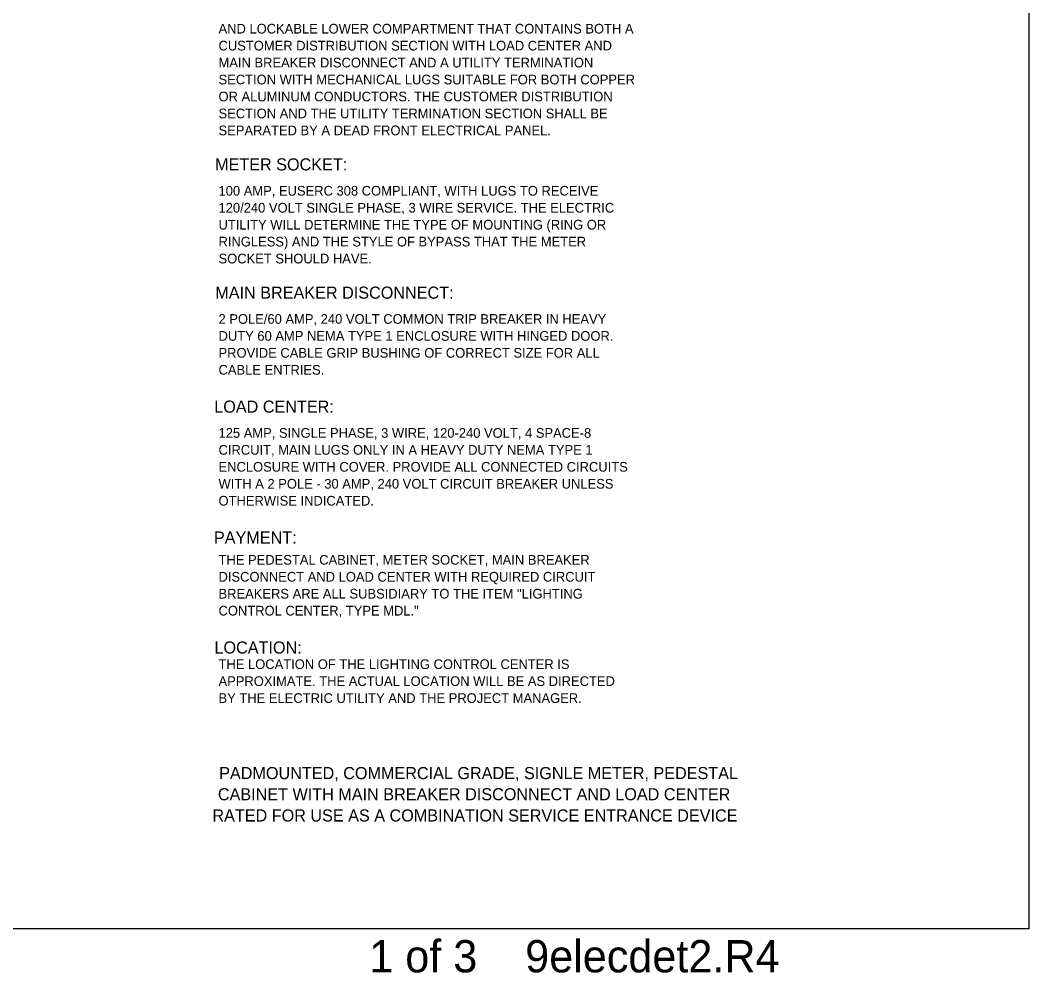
# Model space of a CAD drawing. Extents: x 99992 to 113392, y 99794 to 102182.
# Drawn here: x 101942 to 103192, y 99831 to 101011 of the extents above; entities that cross this region are included whole.
import ezdxf

# ---------------------------------------------------------------- set-up
doc = ezdxf.new("R2010")
doc.units = 0
for name, color, linetype in [('Border Line', 7, 'Continuous'), ('Border Organizer Shape', 7, 'Continuous'), ('Default', 7, 'Continuous')]:
    doc.layers.add(name, color=color, linetype=linetype)

msp = doc.modelspace()

# ---------------------------------------------------------------- linework, layer by layer
at = {"layer": 'Default'}
msp.add_lwpolyline([(99992.2, 102085.3), (103191.9, 102085.3), (103191.9, 99885.7), (99992.2, 99885.7)], close=True, dxfattribs=at)

# ---------------------------------------------------------------- texts
at = {"layer": 'Border Line'}
msp.add_text('1 of 3    9elecdet2.R4', height=40, dxfattribs=at).set_placement((102374.4, 99831.7))
at = {"layer": 'Border Organizer Shape'}
for s, height, p in [('AND LOCKABLE LOWER COMPARTMENT THAT CONTAINS BOTH A ', 12, (102187.5, 100994.8)), ('CUSTOMER DISTRIBUTION SECTION WITH LOAD CENTER AND ', 12, (102187.5, 100973.8)), ('MAIN BREAKER DISCONNECT AND A UTILITY TERMINATION ', 12, (102187.5, 100952.8)), ('SECTION WITH MECHANICAL LUGS SUITABLE FOR BOTH COPPER ', 12, (102187.5, 100931.8)), ('OR ALUMINUM CONDUCTORS. THE CUSTOMER DISTRIBUTION ', 12, (102187.5, 100910.8)), ('SECTION AND THE UTILITY TERMINATION SECTION SHALL BE ', 12, (102187.5, 100889.8)), ('SEPARATED BY A DEAD FRONT ELECTRICAL PANEL.', 12, (102187.5, 100868.8)), ('METER SOCKET:', 15, (102183.2, 100825.2)), ('100 AMP, EUSERC 308 COMPLIANT, WITH LUGS TO RECEIVE ', 12, (102187.5, 100794)), ('120/240 VOLT SINGLE PHASE, 3 WIRE SERVICE. THE ELECTRIC ', 12, (102187.5, 100773)), ('UTILITY WILL DETERMINE THE TYPE OF MOUNTING (RING OR ', 12, (102187.5, 100752)), ('RINGLESS) AND THE STYLE OF BYPASS THAT THE METER ', 12, (102187.5, 100731)), ('SOCKET SHOULD HAVE.', 12, (102187.5, 100710)), ('MAIN BREAKER DISCONNECT:', 15, (102183.5, 100666.3)), ('2 POLE/60 AMP, 240 VOLT COMMON TRIP BREAKER IN HEAVY ', 12, (102187.5, 100635.2)), ('DUTY 60 AMP NEMA TYPE 1 ENCLOSURE WITH HINGED DOOR. ', 12, (102187.5, 100614.2)), ('PROVIDE CABLE GRIP BUSHING OF CORRECT SIZE FOR ALL ', 12, (102187.5, 100593.2)), ('CABLE ENTRIES.', 12, (102187.5, 100572.2)), ('LOAD CENTER:', 15, (102182.2, 100525.1)), ('125 AMP, SINGLE PHASE, 3 WIRE, 120-240 VOLT, 4 SPACE-8 ', 12, (102187.5, 100494)), ('CIRCUIT, MAIN LUGS ONLY IN A HEAVY DUTY NEMA TYPE 1 ', 12, (102187.5, 100473)), ('ENCLOSURE WITH COVER. PROVIDE ALL CONNECTED CIRCUITS ', 12, (102187.5, 100452)), ('WITH A 2 POLE - 30 AMP, 240 VOLT CIRCUIT BREAKER UNLESS ', 12, (102187.5, 100431)), ('OTHERWISE INDICATED.', 12, (102187.5, 100410)), ('PAYMENT:', 15, (102181.8, 100362.9)), ('THE PEDESTAL CABINET, METER SOCKET, MAIN BREAKER ', 12, (102187.5, 100336.8)), ('DISCONNECT AND LOAD CENTER WITH REQUIRED CIRCUIT ', 12, (102187.5, 100315.8)), ('BREAKERS ARE ALL SUBSIDIARY TO THE ITEM "LIGHTING ', 12, (102187.5, 100294.8)), ('CONTROL CENTER, TYPE MDL."', 12, (102187.5, 100273.8)), ('LOCATION:', 15, (102182.5, 100226.7)), ('THE LOCATION OF THE LIGHTING CONTROL CENTER IS ', 12, (102187.5, 100207.5)), ('APPROXIMATE. THE ACTUAL LOCATION WILL BE AS DIRECTED ', 12, (102187.5, 100186.5)), ('BY THE ELECTRIC UTILITY AND THE PROJECT MANAGER.', 12, (102187.5, 100165.5)), ('PADMOUNTED, COMMERCIAL GRADE, SIGNLE METER, PEDESTAL', 15, (102188.3, 100071.1)), ('CABINET WITH MAIN BREAKER DISCONNECT AND LOAD CENTER   ', 15, (102186.7, 100044.9)), ('RATED FOR USE AS A COMBINATION SERVICE ENTRANCE DEVICE', 15, (102179.9, 100018.6))]:
    msp.add_text(s, height=height, dxfattribs=at).set_placement(p)

doc.saveas('drawing.dxf')
